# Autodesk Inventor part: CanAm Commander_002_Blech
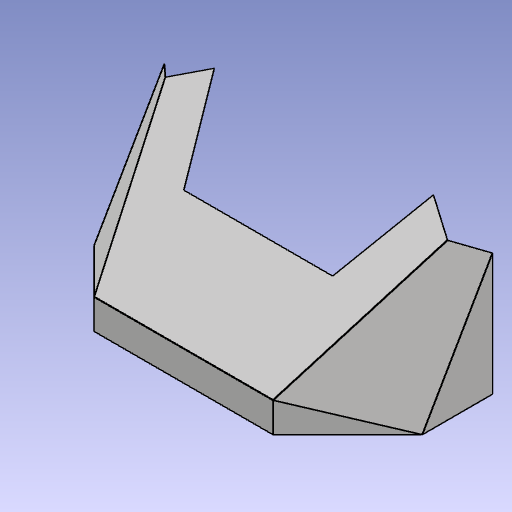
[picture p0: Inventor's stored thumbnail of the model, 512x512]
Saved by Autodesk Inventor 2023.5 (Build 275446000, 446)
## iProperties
Part Number: CanAm Commander_002_Blech
Material: Generisch
Document SubType Name: Blech
Designer: wondraschek
Density: 1 g/cm^3
Flat Pattern Width: 35.7278 cm
Flat Pattern Length: 83.9921 cm
Flat Pattern Area: 3000.86 cm^2
Sheet Metal Rule: Standard_mm
Sheet Metal Width: 357,278 mm
Sheet Metal Length: 839,921 mm
Sheet Metal Area: 300085,572 mm^2
Appearance: Vorgabe
Author: wondraschek
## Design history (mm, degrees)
derived "CanAm Commander_SKI.ipt"
sketch "Skizze1"
  geometry: L1 (386.711, 268.86)-(300, 0) reference; L2 (300, 0)-(0, 0) reference; L3 (0, 0)-(-86.711, 268.86) reference; L4 (-86.711, 268.86)-(-33.976, 307.116) reference; L5 (-33.976, 307.116)-(25, 163.351) reference; L6 (25, 163.351)-(275, 163.351) reference; L7 (275, 163.351)-(333.976, 307.116) reference; L8 (333.976, 307.116)-(386.711, 268.86) reference; 1 further point
  node "Schnittkanten projizieren1"
sketch "Skizze2"
  geometry: L1 (0, 282.497)-(-48.734, 310.178) reference; L2 (0, 0)-(0, 282.497) reference; L3 (-48.734, 310.178)-(-154.81, 98.913) reference; L4 (-154.81, 98.913)-(0, 0) reference; 1 further point
sketch "Skizze3"
  geometry: L1 (0, 117.788)-(204.965, 117.788) reference; L2 (204.965, 117.788)-(0, 0) reference; L3 (0, 0)-(0, 117.788) reference; 1 further point
sketch "Skizze4"
  geometry: L1 (176.777, 50)-(0, 0) reference; L2 (0, 50)-(0, 0) reference; L3 (0, 50)-(176.777, 50) reference; 1 further point
sketch "Skizze5"
  geometry: L1 (300, 50)-(0, 50) reference; L2 (0, 0)-(0, 50) reference; L3 (300, 0)-(0, 0) reference; L4 (300, 0)-(300, 50) reference; 1 further point
node "Fläche2"
node "Fläche3"
node "Fläche4"
node "Fläche5"
node "Fläche6"
mirror "Spiegeln1"
feature "Biegung11" dims "d2" = 0.5 (= Stärke), "d57" = 0.5 (= BreiteBiegungsfreistellung), "d58" = 0.25 (= TiefeBiegungsfreistellung), "d59" = 1 (= MinimalRest), "d60" = 0.5 (= Übergangsradius), "d61" = 0.5 (= Biegeradius), "AbstandVerbindung" = 0.01
  node "Volumenkörper3"
feature "Biegung12" dims "d5" = 0.5 (= Stärke), "d62" = 0.5 (= BreiteBiegungsfreistellung), "d63" = 0.25 (= TiefeBiegungsfreistellung), "d64" = 1 (= MinimalRest), "d65" = 0.5 (= Übergangsradius), "d66" = 0.5 (= Biegeradius), "AbstandVerbindung" = 0.01
  node "Volumenkörper2"
feature "Biegung14" dims "d4" = 0.5 (= Stärke), "d72" = 0.5 (= BreiteBiegungsfreistellung), "d73" = 0.25 (= TiefeBiegungsfreistellung), "d74" = 1 (= MinimalRest), "d75" = 0.5 (= Übergangsradius), "d76" = 0.5 (= Biegeradius), "AbstandVerbindung" = 0.01
  node "Volumenkörper5"
feature "Biegung15" dims "d3" = 0.5 (= Stärke), "d77" = 0.5 (= BreiteBiegungsfreistellung), "d78" = 0.25 (= TiefeBiegungsfreistellung), "d79" = 1 (= MinimalRest), "d80" = 0.5 (= Übergangsradius), "d81" = 0.5 (= Biegeradius), "AbstandVerbindung" = 0.01
  node "Volumenkörper4"
feature "Biegung16" dims "d5" = 0.5 (= Stärke), "d82" = 0.5 (= BreiteBiegungsfreistellung), "d83" = 0.25 (= TiefeBiegungsfreistellung), "d84" = 1 (= MinimalRest), "d85" = 0.5 (= Übergangsradius), "d86" = 0.5 (= Biegeradius), "AbstandVerbindung" = 0.01
  node "Volumenkörper7"
feature "Biegung17" dims "d4" = 0.5 (= Stärke), "d87" = 0.5 (= BreiteBiegungsfreistellung), "d88" = 0.25 (= TiefeBiegungsfreistellung), "d89" = 1 (= MinimalRest), "d90" = 0.5 (= Übergangsradius), "d91" = 0.5 (= Biegeradius), "AbstandVerbindung" = 0.01
  node "Volumenkörper9"
feature "Biegung18" dims "d4" = 0.5 (= Stärke), "d92" = 0.5 (= BreiteBiegungsfreistellung), "d93" = 0.25 (= TiefeBiegungsfreistellung), "d94" = 1 (= MinimalRest), "d95" = 0.5 (= Übergangsradius), "d96" = 0.5 (= Biegeradius), "AbstandVerbindung" = 0.01
  node "Volumenkörper6"
tag "Bezeichnung1"
feature "Grobblech2" dims "d2" = 0.5 (= Stärke)
feature "Grobblech3" dims "d3" = 0.5 (= Stärke)
feature "Grobblech4" dims "d4" = 0.5 (= Stärke)
feature "Grobblech5" dims "d5" = 0.5 (= Stärke)
feature "Grobblech6" dims "d6" = 0.5 (= Stärke)
feature "Anordnung von Volumenkörper3:1"
feature "Anordnung von Volumenkörper4:2"
node "Volumenkörper8"
feature "Anordnung von Volumenkörper5:3"
feature "Volumenkörper1::CanAm Commander_SKI.ipt"
node "Flä1"
feature "Definition1"
other parameters: "Stärke" = 0.5 (derived), "KFaktor" = 4.4, "Biegeradius" = 0.5 (= Stärke), "BreiteBiegungsfreistellung" = 0.5 (= Stärke), "TiefeBiegungsfreistellung" = 0.25 (= 0.5 x Stärke), "GrößeEckenfreistellung" = 2 (= 4 x Stärke), "MinimalRest" = 1 (= 2 x Stärke), "Übergangsradius" = 0.5 (= Biegeradius), "JacobiRadiusGröße" = 0.5 (= Biegeradius), "Abstandsgröße" = 0.5 (= Stärke), "Abstandsgröße" = 0.5, "Biegeradius" = 0.5, "BreiteBiegungsfreistellung" = 0.5, "GrößeEckenfreistellung" = 2, "JacobiRadiusGröße" = 0.5, "MinimalRest" = 1, "Stärke" = 0.5, "TiefeBiegungsfreistellung" = 0.25, "Übergangsradius" = 0.5
